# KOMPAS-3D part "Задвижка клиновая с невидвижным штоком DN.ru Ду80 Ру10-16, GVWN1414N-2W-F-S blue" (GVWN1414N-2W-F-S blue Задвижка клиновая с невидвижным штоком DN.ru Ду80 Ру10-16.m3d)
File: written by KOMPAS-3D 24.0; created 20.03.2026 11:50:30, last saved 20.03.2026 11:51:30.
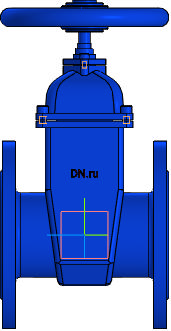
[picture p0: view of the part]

Document properties: Автор: R2D2; Полное имя файла: E:\Работа\Зайцев\GVWN1414N-2W-F-S blue Задвижка клиновая с невидвижным штоком DN.ru Ду40-300 Ру10-16\DN80\GVWN1414N-2W-F-S blue Задвижка клиновая с невидвижным штоком DN.ru Ду80 Ру10-16.m3d

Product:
- Component [detail]: Задвижка клиновая с невидвижным штоком DN.ru Ду40-300 Ру10-16  | designation GVWN1414N-2W-F-S blue  | qty 1  | pos. 1  | Раздел спецификации: Прочие изделия; source file: исходные материалы\корпус.m3d
- Component [detail]: Фланец  | qty 2  | pos. 2  | Автор: R2D2; additional columns: Типовые; source file: исходные материалы\Фланец DN80 PN10-16 b16.5.m3d
- Component [detail]: штурвал  | qty 1  | pos. 3  | Автор: R2D2; additional columns: Типовые; source file: исходные материалы\штурвал.m3d
- Component [standard]: Hexagon socket head cap screw ISO 4762 - М8 x 12  | qty 2  | pos. 4  | Материал: Не определено (density 0 kg/m3); Масса: 0.0109; Раздел спецификации: Стандартные изделия; Рассекать на разрезах: no
- Component [standard]: Hexagon socket head cap screw ISO 4762 - М8 x 12  | qty 1  | pos. 5  | Материал: Не определено (density 0 kg/m3); Масса: 0.0109; Раздел спецификации: Стандартные изделия; Рассекать на разрезах: no
- Component [standard]: Hexagon socket head cap screw ISO 4762 - М8 x 12  | qty 1  | Материал: Не определено (density 0 kg/m3); Масса: 0.0109; Раздел спецификации: Стандартные изделия; Рассекать на разрезах: no
- Component [standard]: Hexagon socket head cap screw ISO 4762 - М6 x 10  | qty 1  | pos. 4  | Материал: Не определено (density 0 kg/m3); Масса: 0.0047; Раздел спецификации: Стандартные изделия; Рассекать на разрезах: no
- Component [standard]: Hexagon socket head cap screw ISO 4762 - М6 x 10  | qty 1  | Материал: Не определено (density 0 kg/m3); Масса: 0.0047; Раздел спецификации: Стандартные изделия; Рассекать на разрезах: no
- Part/product: Задвижка клиновая с невидвижным штоком DN.ru Ду80 Ру10-16  | designation GVWN1414N-2W-F-S blue
    Масса: 11
    Раздел спецификации: Прочие изделия
    Примечание: D040-10581

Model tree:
1. Масштабирование:1
2. Масштабирование : Тело 1
     Масштаб по оси Х = 1; Масштаб по оси Y = 1; Масштаб по оси Z = 1; Коэффициент = 1.2
3. Элемент выдавливания:1  (with: Грань.Элемент выдавливания:2, Грань.Элемент вращения:1)
     Расстояние 1 = 25.5
4. Элемент выдавливания:2  (with: Грань.Элемент выдавливания:1, Грань.Элемент вращения:1)
     Расстояние 1 = 25.5
5. Скругление:1  (with: Ребро.Элемент выдавливания:2, Ребро.Элемент выдавливания:1, Грань.Элемент вращения:1, Грань.Элемент выдавливания:12, Грань.Элемент выдавливания:5, Грань.Скругление:6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)  (labels: Грань.Твердое тело1)
     Радиус = 5; Расстояние = -90; Ориентация = 2; Расстояние = -250

Referenced files in E:\Работа\Зайцев\GVWN1414N-2W-F-S blue Задвижка клиновая с невидвижным штоком DN.ru Ду40-300 Ру10-16\DN80\исходные материалы\: корпус.m3d, штурвал.m3d, Фланец DN80 PN10-16 b16.5.m3d
Referenced files in C:\Program Files\ASCON\KOMPAS-3D v24\Libs\PolynomLib\DATA\vault\Methods\Kompas\3D\: PLib_Screw_DIN_7984_1500.m3d
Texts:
  BOSimple***PART:b7fb87e8-e11b-0771-c746-2cb1e6324b0d***SHORTLOC:A259_235BDFABBEFC4171[1,25;12;8;-;Undefined]
  BOSimple***PART:86906dfe-320b-4a65-fedb-73bd2ba9e651***SHORTLOC:A259_235BDFABBEFC4171[1;10;6;-;Undefined]
  GVWN1414N-2W-F-S blue
  GVWN1414N-2W-F-S blue Задвижка клиновая с невидвижным штоком DN.ru Ду40-300 Ру10-16
  Фланец (1)
  Hexagon socket head cap screw ISO 4762 - М8 x 12 (1)
  Hexagon socket head cap screw ISO 4762 - М8 x 12 (2)
  Hexagon socket head cap screw ISO 4762 - М8 x 12 (3)
  Hexagon socket head cap screw ISO 4762 - М8 x 12 (4)
  Hexagon socket head cap screw ISO 4762 - М6 x 10 (1)
  Hexagon socket head cap screw ISO 4762 - М6 x 10 (2)
  Фланец (2)
  Ось Z.Начало координат
  Плоскость ZX.Начало координат
  Плоскость XY.Начало координат
  Твердое тело1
